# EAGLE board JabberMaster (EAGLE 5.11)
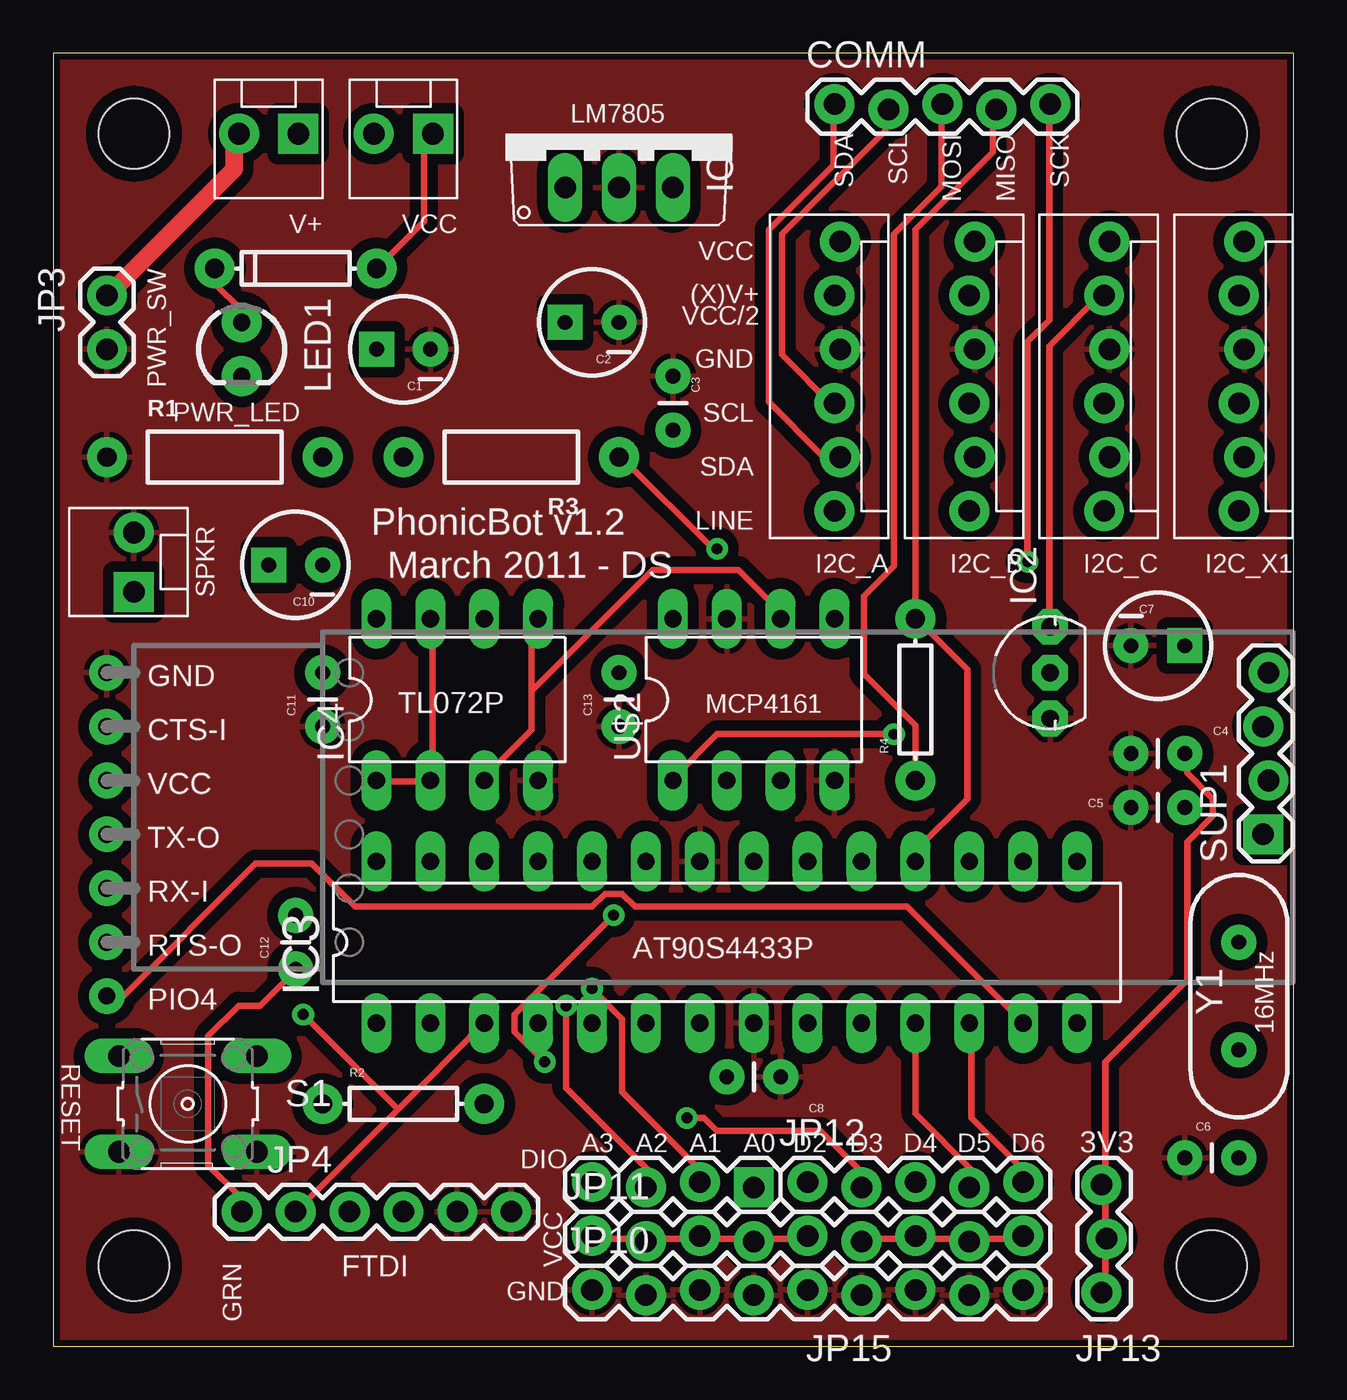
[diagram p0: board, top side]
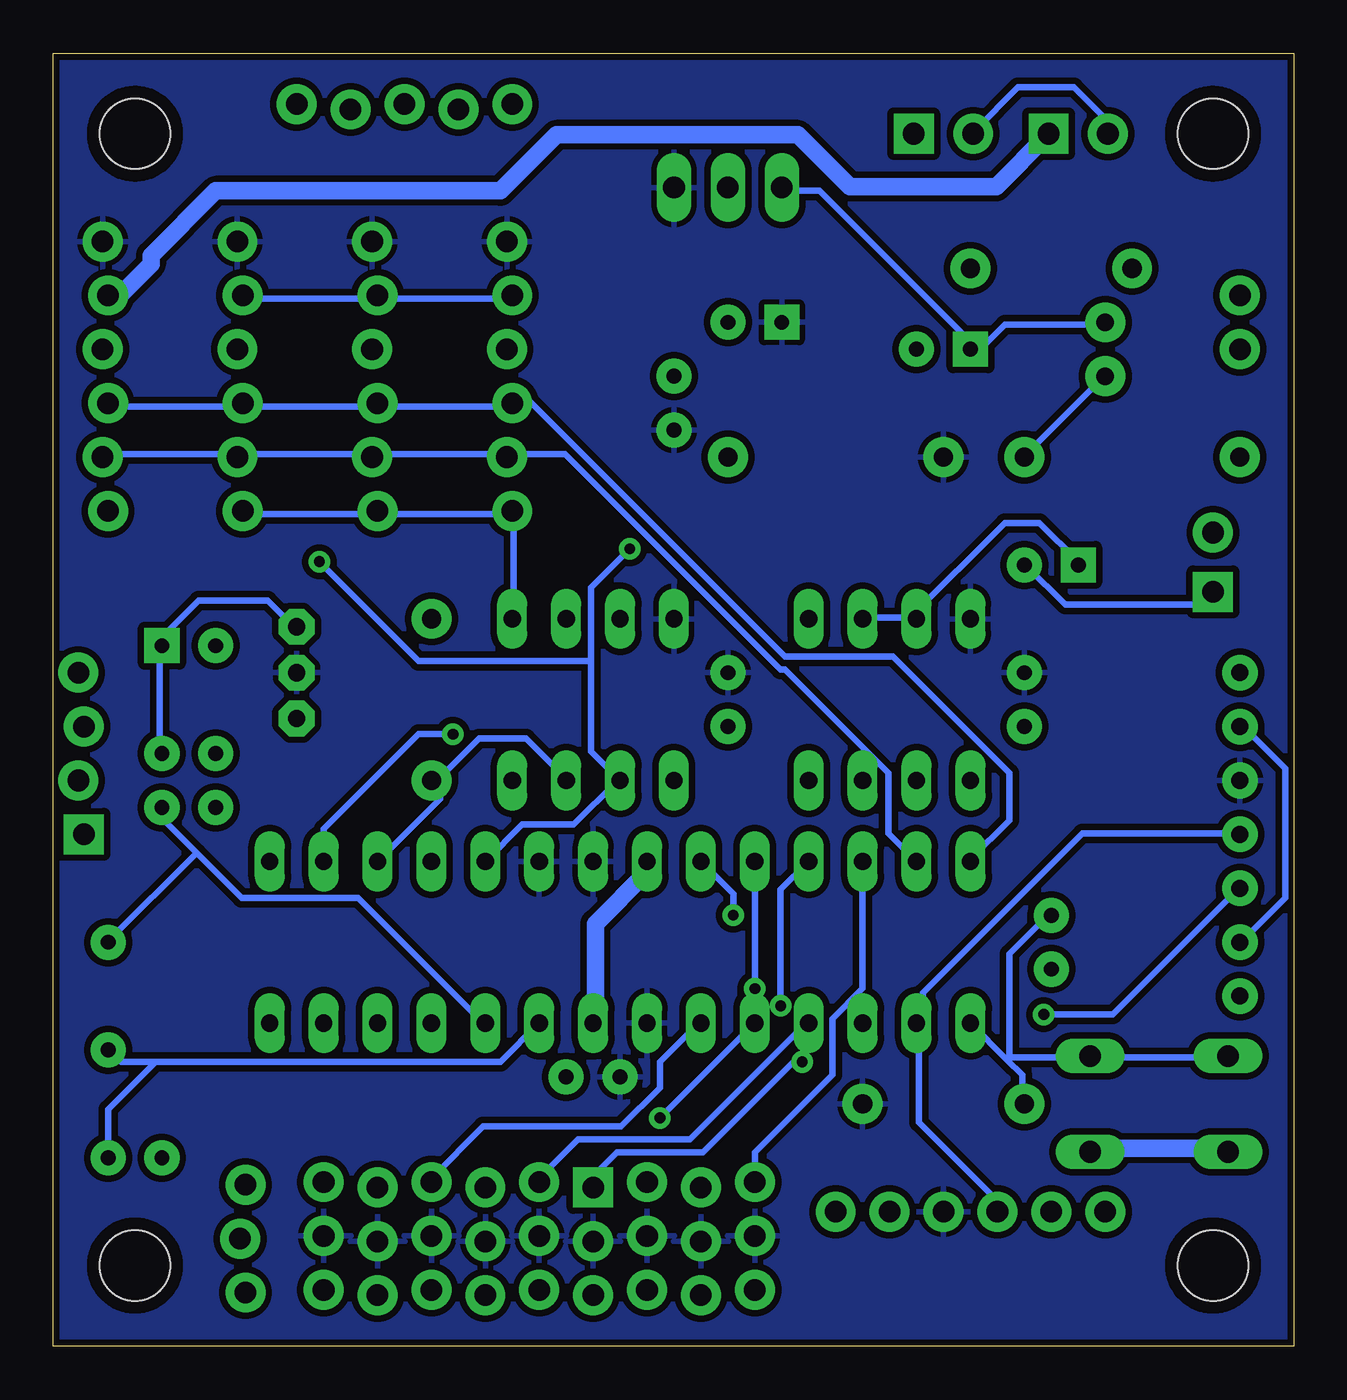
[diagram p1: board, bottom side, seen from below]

Size 58.47 x 60.95 mm. Coordinates in mm from the lower left corner, seen from the top.
Outline: 0,0 58.47,0 58.47,60.95 0,60.95 0,0
Copper layers (1*16): Top 0.035mm / dielectric 1.5mm / Bottom 0.035mm
Design rules "SparkFun": minimum track width 12mil, minimum drill 20mil, track to track 8mil, track to pad 8mil, pad to pad 8mil, via to via 8mil, smd to smd 8mil, copper to edge 10mil, drill to drill 8mil, minimum pad ring 12mil, minimum via ring 10mil, stop-mask expansion 4mil, vias tented up to drill 25mil, thermal gap 10mil
Net classes: 1 power: width 0.813 mm, clearance 0.508 mm

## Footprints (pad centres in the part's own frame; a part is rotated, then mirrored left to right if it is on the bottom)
BLUETOOTH_MATE_90FEMALE = drill 0.8 pad 1.676 round: CTS-I 0,10.16; GND 0,12.7; PIO4 0,-2.54; RTS-O 0,0; RX-I 0,2.54; TX-O 0,5.08; VCC 0,7.62
CPOL-RADIAL-10UF-25V = drill 0.7 pad 1.651 square: 1 1.27,0 | drill 0.7 pad 1.651 round: 2 -1.27,0
CAP-PTH-SMALL = drill 0.7 pad 1.651 round: 1 0,0; 2 2.54,0
1X05_LOCK = drill 1.016 pad 1.88 round: 1 0,0.127; 2 2.54,-0.127; 3 5.08,0.127; 4 7.62,-0.127; 5 10.16,0.127
DIODE-1N4148 = drill 0.9 pad 1.88 round: A -3.81,0; C 3.81,0
MOLEX-1X6_LOCK = drill 1.016 pad 1.88 round: 1 0,0; 2 2.54,-0.254; 3 5.08,0; 4 7.62,-0.254; 5 10.16,0; 6 12.7,-0.254
TO220V = drill 1.016 long: 1 -2.54,-2.54; 2 0,-2.54; 3 2.54,-2.54
TO92-INLINE = drill 0.813 pad 1.676 octagon: 1 -2.159,0; 2 0,0; 3 2.159,0
DIL28-3 = drill 0.813 long: 1 -16.51,-3.81; 2 -13.97,-3.81; 3 -11.43,-3.81; 4 -8.89,-3.81; 5 -6.35,-3.81; 6 -3.81,-3.81; 7 -1.27,-3.81; 8 1.27,-3.81; 9 3.81,-3.81; 10 6.35,-3.81; 11 8.89,-3.81; 12 11.43,-3.81; 13 13.97,-3.81; 14 16.51,-3.81; 15 16.51,3.81; 16 13.97,3.81; 17 11.43,3.81; 18 8.89,3.81; 19 6.35,3.81; 20 3.81,3.81; 21 1.27,3.81; 22 -1.27,3.81; 23 -3.81,3.81; 24 -6.35,3.81; 25 -8.89,3.81; 26 -11.43,3.81; 27 -13.97,3.81; 28 -16.51,3.81
DIL08 = drill 0.813 long: 1 -3.81,-3.81; 2 -1.27,-3.81; 3 1.27,-3.81; 4 3.81,-3.81; 5 3.81,3.81; 6 1.27,3.81; 7 -1.27,3.81; 8 -3.81,3.81
MOLEX-1X2_LOCK = drill 1.016 pad 1.88 square: 1 -0.127,0 | drill 1.016 pad 1.88 round: 2 2.667,0
1X02 = drill 1.016 pad 1.88 round: 1 0,0; 2 2.54,0
FTDI_BASIC = drill 1.016 pad 1.88 round: CTS 10.16,0; DTR 0,0; GND 12.7,0; RXI 2.54,0; TXO 5.08,0; VCC 7.62,0
STAND-OFF = hole 3.302: 0,0
1X09_LOCK = drill 1.016 pad 1.88 round: 1 0,0.127; 2 2.54,-0.127; 3 5.08,0.127; 4 7.62,-0.127; 5 10.16,0.127; 6 12.7,-0.127; 7 15.24,0.127; 8 17.78,-0.127; 9 20.32,0.127
1X03_LOCK = drill 1.016 pad 1.88 round: 1 0,0.127; 2 2.54,-0.127; 3 5.08,0.127
1X04_LOCK = drill 1.016 pad 1.88 square: 1 0,0.127 | drill 1.016 pad 1.88 round: 2 2.54,-0.127; 3 5.08,0.127; 4 7.62,-0.127
LED3MM = drill 0.813 pad 1.88 round: A -1.27,0; K 1.27,0
AXIAL-0.4 = drill 0.9 pad 1.88 round: P$1 -5.08,0; P$2 5.08,0
AXIAL-0.3 = drill 0.9 pad 1.88 round: P$1 -3.81,0; P$2 3.81,0
B3F-10XX = drill 1.016 long: 1 -3.251,2.261; 2 3.251,2.261; 3 -3.251,-2.261; 4 3.251,-2.261
HC49US = drill 0.7 pad 1.651 round: 1 -2.54,0; 2 2.54,0

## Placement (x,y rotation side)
BTM8  BLUETOOTH_MATE_SILVER  [BLUETOOTH_MATE_90FEMALE]  2.54,19.05 0 top
C1  10uF  [CPOL-RADIAL-10UF-25V]  16.51,46.99 180 top
C2  10uF  [CPOL-RADIAL-10UF-25V]  25.4,48.26 180 top
C3  0.1uF  [CAP-PTH-SMALL]  29.21,43.18 90 top
C4  0.1uF  [CAP-PTH-SMALL]  53.34,27.94 180 top
C5  22Pf  [CAP-PTH-SMALL]  50.8,25.4 0 top
C6  22pF  [CAP-PTH-SMALL]  53.34,8.89 0 top
C7  10uF  [CPOL-RADIAL-10UF-25V]  52.07,33.02 0 top
C8  0.1uF  [CAP-PTH-SMALL]  34.29,12.7 180 top
C10  100uF  [CPOL-RADIAL-10UF-25V]  11.43,36.83 180 top
C11  0.1uF  [CAP-PTH-SMALL]  12.7,29.21 90 top
C12  0.1uF  [CAP-PTH-SMALL]  11.43,17.78 90 top
C13  0.1uF  [CAP-PTH-SMALL]  26.67,29.21 90 top
COMM  [1X05_LOCK]  36.83,58.42 0 top
D1  [DIODE-1N4148]  11.43,50.8 180 top
I2C_A  [MOLEX-1X6_LOCK]  36.83,39.37 90 top
I2C_B  [MOLEX-1X6_LOCK]  43.18,39.37 90 top
I2C_C  [MOLEX-1X6_LOCK]  49.53,39.37 90 top
I2C_X1  [MOLEX-1X6_LOCK]  55.88,39.37 90 top
IC1  LM7805  [TO220V]  26.67,57.15 0 top
IC2  MCP1700  [TO92-INLINE]  46.99,31.75 90 top
IC3  AT90S4433P  [DIL28-3]  31.75,19.05 0 top
IC4  TL072P  [DIL08]  19.05,30.48 0 top
JP1  VCC  [MOLEX-1X2_LOCK]  17.78,57.15 180 top
JP2  V+  [MOLEX-1X2_LOCK]  11.43,57.15 180 top
JP3  PWR_SW  [1X02]  2.54,49.53 270 top
JP4  FTDI  [FTDI_BASIC]  8.89,6.35 0 top
JP5  STAND-OFF  [STAND-OFF]  54.61,3.81 0 top
JP6  SPKR  [MOLEX-1X2_LOCK]  3.81,35.69 90 top
JP7  STAND-OFF  [STAND-OFF]  54.61,57.15 0 top
JP8  STAND-OFF  [STAND-OFF]  3.81,3.81 0 top
JP9  STAND-OFF  [STAND-OFF]  3.81,57.15 0 top
JP10  GND  [1X09_LOCK]  25.4,2.54 0 top
JP11  VCC  [1X09_LOCK]  25.4,5.08 0 top
JP12  DIO2  [1X05_LOCK]  35.56,7.62 0 top
JP13  3V3  [1X03_LOCK]  49.53,2.54 90 top
JP15  DIO  [1X04_LOCK]  33.02,7.62 180 top
LED1  PWR_LED  [LED3MM]  8.89,46.99 270 top
R1  220  [AXIAL-0.4]  7.62,41.91 0 top
R2  10K  [AXIAL-0.3]  16.51,11.43 0 top
R3  1K5  [AXIAL-0.4]  21.59,41.91 180 top
R4  220K  [AXIAL-0.3]  40.64,30.48 90 top
S1  RESET  [B3F-10XX]  6.35,11.43 0 top
SUP1  DIO  [1X04_LOCK]  57.15,24.13 90 top
U$2  MCP4161  [DIL08]  33.02,30.48 0 top
Y1  16MHz  [HC49US]  55.88,16.51 90 top

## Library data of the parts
BTM8 U$2 = Dek
C1-C8 C10-C13 COMM D1 I2C_A I2C_B I2C_C I2C_X1 JP1-JP13 JP15 LED1 R1-R4 SUP1 Y1 = SparkFun
IC1 IC4 = linear
IC2 = adafruit
IC3 = atmel; OC_FARNELL: unknown; OC_NEWARK: unknown
S1 = switch-omron; MPN: B3F-1000; OC_FARNELL: 176432; OC_NEWARK: 36M3542

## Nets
A0: IC3.23 JP15.1
A1: IC3.24 JP15.2
A2: IC3.25 JP15.3
A3: IC3.26 JP15.4
BUF_IN: IC4.3 IC4.5 U$2.6
D2: IC3.4 JP12.1
D3: IC3.5 JP12.2
D4: IC3.6 JP12.3
D5: IC3.11 JP12.4
D6: IC3.12 JP12.5
D9: IC3.15
DTR: C12.1 JP4.DTR
GND [power]: BTM8.GND C1.2 C2.2 C3.2 C4.2 C5.1 C6.1 C7.2 C8.1 C11.1 C13.1 I2C_A.4 I2C_B.4 I2C_C.4 I2C_X1.4 IC1.2 IC2.1 IC3.8 IC3.22 IC4.4 JP3.2 JP4.CTS JP4.GND JP6.2 JP10.1 JP10.2 JP10.3 JP10.4 JP10.5 JP10.6 JP10.7 JP10.8 JP10.9 R1.P$1 S1.3 S1.4 U$2.4 U$2.7
LINE_A: I2C_A.1 I2C_B.1 I2C_C.1 U$2.5
LINE_M: I2C_X1.1
MISO: COMM.4 IC3.18 R4.P$2
MOSI: COMM.3 IC3.17 R4.P$1 U$2.3
N$2: C12.2 IC3.1 R2.P$1 S1.1 S1.2
N$3: D1.A JP1.1
N$4: C1.1 D1.C IC1.1 LED1.A
N$5: C10.2 JP6.1
N$6: LED1.K R1.P$2
N$7 [power]: JP1.2 JP2.2 JP3.1
N$8: C10.1 IC4.1 IC4.2 IC4.6 IC4.7
N$10: BTM8.CTS-I BTM8.RTS-O
PIO4: BTM8.PIO4 IC3.13
RX: BTM8.TX-O IC3.2 JP4.TXO
SCK: COMM.5 IC3.19 R3.P$1 U$2.2
SCL: COMM.2 I2C_A.3 I2C_B.3 I2C_C.3 I2C_X1.3 IC3.28
SDA: COMM.1 I2C_A.2 I2C_B.2 I2C_C.2 I2C_X1.2 IC3.27
TX: BTM8.RX-I IC3.3 JP4.RXI
V+ [power]: I2C_X1.5 JP2.1
VCC: BTM8.VCC C2.1 C3.1 C8.2 C11.2 C13.2 I2C_A.6 I2C_B.6 I2C_C.6 I2C_X1.6 IC1.3 IC2.2 IC3.7 IC3.20 IC3.21 IC4.8 JP4.VCC JP11.1 JP11.2 JP11.3 JP11.4 JP11.5 JP11.6 JP11.7 JP11.8 JP11.9 R2.P$2 R3.P$2 U$2.8
VCC/2: C4.1 C7.1 I2C_A.5 I2C_B.5 I2C_C.5 IC2.3 JP13.1 JP13.2 JP13.3
VOL_CS: IC3.16 U$2.1
VOL_MUTE: IC3.14
XTAL1: C6.2 IC3.9 Y1.1
XTAL2: C5.2 IC3.10 Y1.2

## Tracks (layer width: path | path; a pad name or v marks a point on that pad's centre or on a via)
A0  (via drill 0.51)
  Top 0.305: v26.42,20.32 21.74,15.65 21.74,14.83 v23.16,13.41
  Bottom 0.305: v26.42,20.32 26.42,21.34 IC3.23 | v23.16,13.41 23.57,13.41 27.84,9.14 31.9,9.14 32.92,8.13 32.92,7.52 JP15.1
A1  (via drill 0.51)
  Top 0.305: v25.4,16.87 26.82,15.44 26.82,11.99 30.48,8.33 JP15.2
  Bottom 0.305: v25.4,16.87 IC3.24
A2  (via drill 0.51)
  Top 0.305: v24.18,16.05 24.18,12.19 28.04,8.33 28.04,7.52 JP15.3
  Bottom 0.305: v24.18,16.05 24.18,21.54 IC3.25
A3
  Bottom 0.305: IC3.26 20.32,16.87 21.74,15.44 21.74,12.8 25.4,9.14 JP15.4
BUF_IN
  Top 0.305: 22.55,30.89 22.55,33.93 22.76,34.14 IC4.5 | 22.55,30.89 22.55,29.06 20.32,26.82 IC4.3 | 22.55,30.89 28.25,36.58 32.31,36.58 34.14,34.75 34.14,34.34 U$2.6
D2
  Bottom 0.305: IC3.4 22.96,15.24 28.45,9.75 33.73,9.75 35.56,7.92 JP12.1
D3  (via drill 0.51)
  Top 0.305: v29.87,10.77 30.68,10.77 31.29,10.16 36.17,10.16 38,8.33 38,7.52 JP12.2
  Bottom 0.305: v29.87,10.77 IC3.5
D4
  Bottom 0.305: IC3.6 28.04,15.24 29.87,13.41 29.87,12.19 31.7,10.36 38.2,10.36 40.64,7.92 JP12.3
D5
  Top 0.305: IC3.11 40.64,10.97 43.28,8.33 43.28,7.52 JP12.4
D6
  Top 0.305: IC3.12 43.28,15.24 43.28,10.77 45.72,8.33 JP12.5
DTR
  Top 0.305: C12.1 11.38,17.68 9.75,16.05 8.74,16.05 7.32,14.63 7.32,8.53 8.74,7.11 8.74,6.5 JP4.DTR
GND
  Bottom 0.813: IC3.8 32.92,15.24 32.92,19.91 30.48,22.35 IC3.22 | S1.4 9.55,9.35 3.25,9.35 S1.3
  pour Top (isolate 0.305): -2.54,62.23 59.69,62.23 59.69,-1.27 -2.54,-1.27
LINE_A
  Bottom 0.305: U$2.5 36.78,34.34 36.78,39.22 I2C_A.1 36.98,39.22 43.08,39.22 I2C_B.1 43.28,39.22 49.38,39.22 I2C_C.1
MISO
  Top 0.305: 40.64,34.34 43.08,31.9 43.08,25.81 40.64,23.37 IC3.18 | 40.64,34.34 40.64,52.63 44.3,56.29 44.3,58.12 COMM.4 | 40.64,34.34 R4.P$2
MOSI
  Top 0.305: COMM.3 41.86,58.52 41.86,54.66 39.62,52.43 39.62,36.78 38.2,35.36 38.2,31.7 40.64,29.26 R4.P$1
  Bottom 0.305: 40.23,26.82 38.41,28.65 36.17,28.65 34.34,26.82 U$2.3 | 40.23,26.82 40.64,26.82 R4.P$1 40.23,26.82 | 40.23,26.82 40.23,25.81 IC3.17
N$2
  Bottom 0.305: S1.1 3.25,13.61 9.55,13.61 S1.2 9.75,13.61 13.41,13.61 | 13.51,13.51 12.8,12.8 12.8,11.58 R2.P$1 | 13.51,13.51 IC3.1 | 13.41,13.61 13.41,18.49 11.58,20.32 C12.2 | 13.41,13.61 13.51,13.51
N$3
  Top 0.305: D1.A 17.48,53.03 17.48,56.69 17.88,57.1 JP1.1
N$4
  Top 0.305: LED1.A 8.74,48.36 8.74,48.97 7.72,49.99 7.72,50.8 D1.C
  Bottom 0.305: 15.24,47.14 15.24,47.35 22.35,54.46 23.98,54.46 IC1.1 | 15.24,47.14 14.63,47.14 13.61,48.16 8.94,48.16 LED1.A | 15.24,47.14 C1.1
N$5
  Bottom 0.305: C10.2 12.6,36.78 10.77,34.95 4.47,34.95 3.86,35.56 JP6.1
N$6
  Bottom 0.305: R1.P$2 12.6,42.06 8.94,45.72 LED1.K
N$7
  Top 0.813: JP3.1 2.64,49.58 8.53,55.47 8.53,56.9 8.74,57.1 JP2.2
  Bottom 0.305: JP1.2 15.04,57.3 13.01,59.33 10.36,59.33 8.94,57.91 8.94,57.3 JP2.2
N$8
  Top 0.305: IC4.1 15.24,26.62 17.68,26.62 IC4.2 17.88,26.82 17.88,34.14 IC4.7
  Bottom 0.305: 18.09,34.34 20.32,34.34 IC4.6 | 18.09,34.34 17.88,34.34 IC4.7 18.09,34.34 | 18.09,34.34 13.61,38.81 11.99,38.81 10.16,36.98 C10.1
N$10
  Bottom 0.305: BTM8.RTS-O 2.44,19.1 0.41,21.13 0.41,27.23 2.44,29.26 BTM8.CTS-I
PIO4
  Top 0.305: IC3.13 40.23,20.73 27.43,20.73 26.82,21.34 26.01,21.34 25.4,20.73 14.22,20.73 12.19,22.76 9.55,22.76 3.25,16.46 2.64,16.46 BTM8.PIO4
RX
  Bottom 0.305: 17.68,15.24 17.68,10.57 14.02,6.91 14.02,6.5 JP4.TXO | 17.68,15.24 17.48,15.44 17.48,16.66 9.96,24.18 2.64,24.18 BTM8.TX-O | 17.68,15.24 IC3.2
SCK  (via drill 0.51)
  Top 0.305: v31.29,37.59 31.09,37.59 26.82,41.86 R3.P$1 | v45.92,36.98 45.92,47.35 46.94,48.36 46.94,58.52 COMM.5
  Bottom 0.305: IC3.19 36.37,24.59 33.93,24.59 31.9,26.62 U$2.2 33.12,28.04 33.12,32.31 | v31.29,37.59 33.12,35.76 33.12,32.31 | v45.92,36.98 41.25,32.31 33.12,32.31
SCL
  Top 0.305: COMM.2 39.22,58.12 39.22,57.3 34.34,52.43 34.34,46.74 36.78,44.3 I2C_A.3
  Bottom 0.305: I2C_X1.3 55.88,44.3 49.58,44.3 I2C_C.3 49.38,44.3 43.28,44.3 I2C_B.3 43.08,44.3 36.98,44.3 I2C_A.3 36.78,44.5 35.97,44.5 23.98,32.51 18.9,32.51 13.41,27.03 13.41,24.79 15.24,22.96 IC3.28
SDA
  Top 0.305: COMM.1 36.78,58.52 36.78,55.68 33.73,52.63 33.73,44.5 36.17,42.06 36.98,42.06 I2C_A.2
  Bottom 0.305: IC3.27 19.1,24.18 19.1,27.03 23.98,31.9 24.18,31.9 34.34,42.06 36.98,42.06 I2C_A.2 37.19,42.06 43.28,42.06 I2C_B.2 43.48,42.06 49.78,42.06 | 49.78,42.06 56.08,42.06 I2C_X1.2 | 49.78,42.06 I2C_C.2
TX  (via drill 0.51)
  Top 0.305: 16.26,11.18 IC3.3 | JP4.RXI 16.26,11.18 | 16.26,11.18 v11.79,15.65
  Bottom 0.305: v11.79,15.65 8.53,15.65 2.64,21.54 BTM8.RX-I
V+
  Bottom 0.813: JP2.1 11.58,57.1 14.02,54.66 20.93,54.66 23.37,57.1 34.75,57.1 37.39,54.46 50.8,54.46 53.85,51.41 53.85,51 55.27,49.58 55.88,49.58 I2C_X1.5
VCC
  Top 0.305: JP11.5 35.56,5.08 33.12,5.08 JP11.4 32.92,5.08 30.48,5.08 | 30.48,5.08 28.04,5.08 JP11.2 27.84,5.08 25.4,5.08 JP11.1 | JP11.9 45.72,5.08 43.28,5.08 JP11.8 43.08,5.08 40.64,5.08 | 40.64,5.08 38.2,5.08 JP11.6 | 40.64,5.08 JP11.7 | 30.48,5.08 JP11.3
  pour Bottom (isolate 0.305): -1.27,62.23 59.69,62.23 59.69,-1.27 -1.27,-1.27
VCC/2
  Top 0.305: 49.58,5.08 49.58,2.64 JP13.1 | 49.58,5.08 49.58,7.52 JP13.3 49.58,7.72 49.58,13.41 53.44,17.27 53.44,23.77 54.66,24.99 54.66,25.81 53.44,27.03 53.44,27.84 C4.1 | 49.58,5.08 JP13.2 | I2C_C.5 49.38,49.38 49.17,49.38 46.94,47.14 46.94,33.93 IC2.3
  Bottom 0.305: I2C_A.5 36.98,49.38 43.08,49.38 I2C_B.5 43.28,49.38 49.38,49.38 I2C_C.5 | C4.1 53.44,28.04 53.44,32.92 C7.1 53.24,33.12 53.24,33.53 51.61,35.15 48.36,35.15 47.14,33.93 IC2.3
VOL_CS  (via drill 0.51)
  Top 0.305: v39.62,28.85 31.29,28.85 29.26,26.82 U$2.1
  Bottom 0.305: v39.62,28.85 41.25,28.85 45.72,24.38 IC3.16
XTAL1
  Bottom 0.305: IC3.9 37.39,13.41 53.65,13.41 | 53.65,13.41 55.27,13.41 55.88,14.02 Y1.1 | 53.65,13.41 55.88,11.18 C6.2
XTAL2
  Bottom 0.305: 51.71,23.27 53.24,24.79 53.24,25.4 C5.2 | 51.71,23.27 49.58,21.13 44.09,21.13 38.2,15.24 IC3.10 | Y1.2 55.88,19.1 51.71,23.27

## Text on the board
tPlace: SDA | SCL | MOSI | MISO | SCK | V+ | VCC | VCC | (X)V+ | VCC/2 | GND | SCL | SDA | LINE | PhonicBot v1.2 | March 2011 - DS | SPKR | A3 | A2 | A1 | A0 | D2 | D3 | D4 | D5 | D6 | GRN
